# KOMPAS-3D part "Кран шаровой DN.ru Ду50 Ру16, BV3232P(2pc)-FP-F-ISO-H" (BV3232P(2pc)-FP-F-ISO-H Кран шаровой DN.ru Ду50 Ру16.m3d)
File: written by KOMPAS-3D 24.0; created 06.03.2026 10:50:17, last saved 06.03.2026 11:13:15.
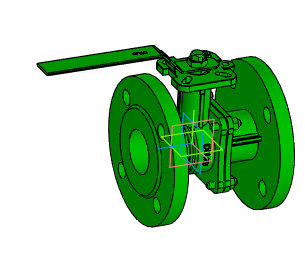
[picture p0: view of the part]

Document properties: Автор: R2D2; Полное имя файла: E:\Работа\Зайцев\BV3232P(2pc)-FP-F-ISO-H Кран шаровой DN.ru Ду15-300 Ру16-40\DN50 PN16\BV3232P(2pc)-FP-F-ISO-H Кран шаровой DN.ru Ду50 Ру16.m3d

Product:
- Part/product: Кран шаровой DN.ru Ду50 Ру16  | designation BV3232P(2pc)-FP-F-ISO-H
    Масса: 8.78
    Раздел спецификации: Прочие изделия
    Форматы листов документа: A2
    Примечание: D160-70652

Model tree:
1. Операция без истории:1

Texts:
  BV3232P(2pc)-FP-F-ISO-H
